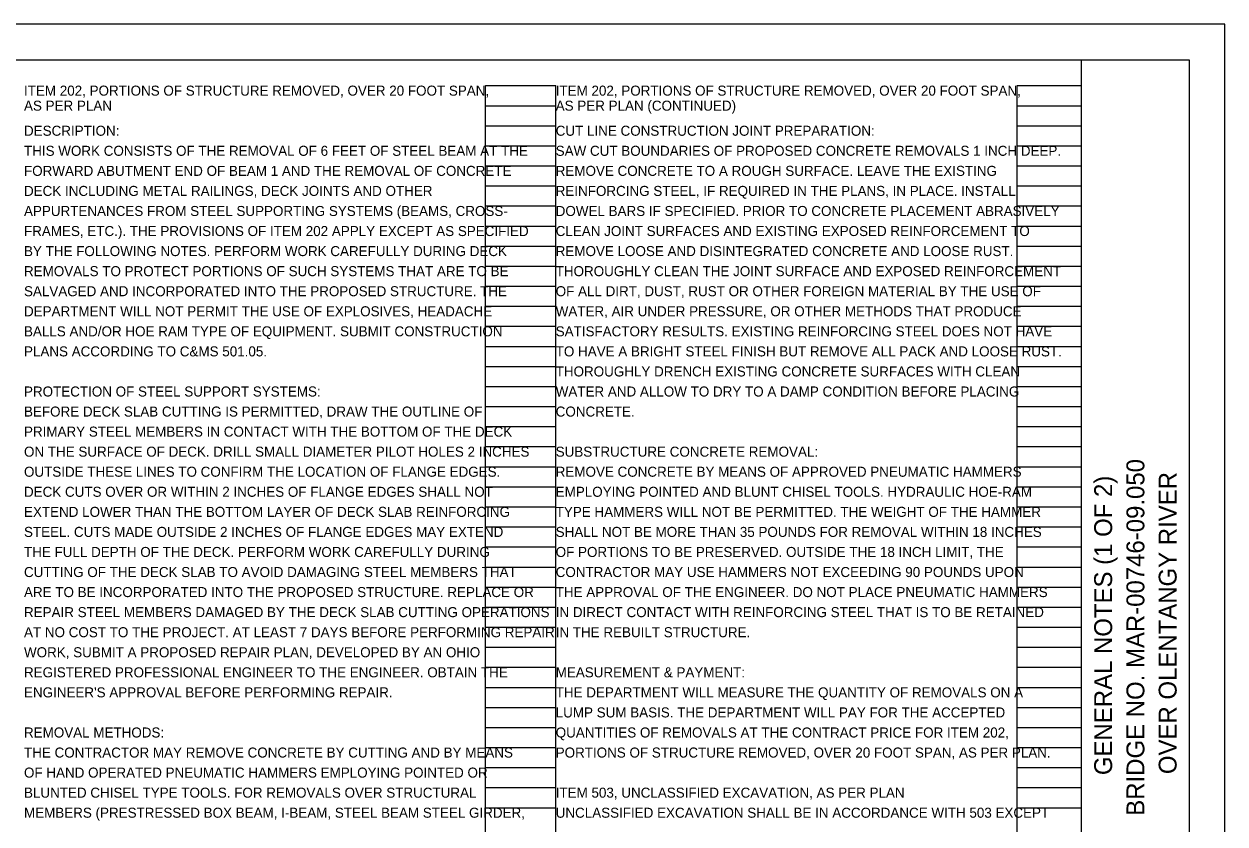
# Model space of a CAD drawing. Extents: x 0 to 34, y 0 to 22.
# Drawn here: x 17.24 to 34, y 10.83 to 22 of the extents above; entities that cross this region are included whole.
import ezdxf

# ---------------------------------------------------------------- set-up
doc = ezdxf.new("R2010")
doc.units = 0
for name, color, linetype in [('SH_Border', 7, 'Continuous'), ('SH_Cut_Line', 7, 'Continuous'), ('SH_Data', 7, 'Continuous'), ('SH_Text', 7, 'Continuous')]:
    doc.layers.add(name, color=color, linetype=linetype)

msp = doc.modelspace()

# ---------------------------------------------------------------- linework, layer by layer
at = {"layer": 'SH_Border'}
msp.add_line((32, 0.5), (32, 21.5), dxfattribs=at)
msp.add_lwpolyline([(1.5, 21.5), (33.5, 21.5), (33.5, 0.5), (1.5, 0.5)], close=True, dxfattribs=at)
at = {"layer": 'SH_Cut_Line'}
msp.add_lwpolyline([(0, 0), (34, 0), (34, 22), (0, 22)], close=True, dxfattribs=at)
at = {"layer": 'SH_Data'}
for p, q in [((23.68, 0.98), (23.68, 21.14)), ((23.68, 21.14), (24.66, 21.14)), ((24.66, 0.98), (24.66, 21.14)), ((31.1, 0.98), (31.1, 21.14)), ((31.1, 21.14), (32, 21.14)), ((32, 0.98), (32, 21.14)), ((23.68, 20.86), (24.66, 20.86)), ((31.1, 20.86), (32, 20.86)), ((23.68, 20.58), (24.66, 20.58)), ((31.1, 20.58), (32, 20.58)), ((23.68, 20.3), (24.66, 20.3)), ((31.1, 20.3), (32, 20.3)), ((23.68, 20.02), (24.66, 20.02)), ((31.1, 20.02), (32, 20.02)), ((23.68, 19.74), (24.66, 19.74)), ((31.1, 19.74), (32, 19.74)), ((23.68, 19.46), (24.66, 19.46)), ((31.1, 19.46), (32, 19.46)), ((23.68, 19.18), (24.66, 19.18)), ((31.1, 19.18), (32, 19.18)), ((23.68, 18.9), (24.66, 18.9)), ((31.1, 18.9), (32, 18.9)), ((23.68, 18.62), (24.66, 18.62)), ((31.1, 18.62), (32, 18.62)), ((23.68, 18.34), (24.66, 18.34)), ((31.1, 18.34), (32, 18.34)), ((23.68, 18.06), (24.66, 18.06)), ((31.1, 18.06), (32, 18.06)), ((23.68, 17.78), (24.66, 17.78)), ((31.1, 17.78), (32, 17.78)), ((23.68, 17.5), (24.66, 17.5)), ((31.1, 17.5), (32, 17.5)), ((23.68, 17.22), (24.66, 17.22)), ((31.1, 17.22), (32, 17.22)), ((23.68, 16.94), (24.66, 16.94)), ((31.1, 16.94), (32, 16.94)), ((23.68, 16.66), (24.66, 16.66)), ((31.1, 16.66), (32, 16.66)), ((23.68, 16.38), (24.66, 16.38)), ((31.1, 16.38), (32, 16.38)), ((23.68, 16.1), (24.66, 16.1)), ((31.1, 16.1), (32, 16.1)), ((23.68, 15.82), (24.66, 15.82)), ((31.1, 15.82), (32, 15.82)), ((23.68, 15.54), (24.66, 15.54)), ((31.1, 15.54), (32, 15.54)), ((23.68, 15.26), (24.66, 15.26)), ((31.1, 15.26), (32, 15.26)), ((23.68, 14.98), (24.66, 14.98)), ((31.1, 14.98), (32, 14.98)), ((23.68, 14.7), (24.66, 14.7)), ((31.1, 14.7), (32, 14.7)), ((23.68, 14.42), (24.66, 14.42)), ((31.1, 14.42), (32, 14.42)), ((23.68, 14.14), (24.66, 14.14)), ((31.1, 14.14), (32, 14.14)), ((23.68, 13.86), (24.66, 13.86)), ((31.1, 13.86), (32, 13.86)), ((23.68, 13.58), (24.66, 13.58)), ((31.1, 13.58), (32, 13.58)), ((23.68, 13.3), (24.66, 13.3)), ((31.1, 13.3), (32, 13.3)), ((23.68, 13.02), (24.66, 13.02)), ((31.1, 13.02), (32, 13.02)), ((23.68, 12.74), (24.66, 12.74)), ((31.1, 12.74), (32, 12.74)), ((23.68, 12.46), (24.66, 12.46)), ((31.1, 12.46), (32, 12.46)), ((23.68, 12.18), (24.66, 12.18)), ((31.1, 12.18), (32, 12.18)), ((23.68, 11.9), (24.66, 11.9)), ((31.1, 11.9), (32, 11.9)), ((23.68, 11.62), (24.66, 11.62)), ((31.1, 11.62), (32, 11.62)), ((23.68, 11.34), (24.66, 11.34)), ((31.1, 11.34), (32, 11.34)), ((23.68, 11.06), (24.66, 11.06)), ((31.1, 11.06), (32, 11.06))]:
    msp.add_line(p, q, dxfattribs=at)

# ---------------------------------------------------------------- texts
for s, p in [('BRIDGE NO. MAR-00746-09.050', (32.875, 10.948)), ('GENERAL NOTES (1 OF 2)', (32.425, 11.515)), ('OVER OLENTANGY RIVER', (33.325, 11.529))]:
    msp.add_text(s, height=0.25, rotation=90, dxfattribs=at).set_placement(p)
at = {"layer": 'SH_Text'}
for s, p in [('ITEM 202, PORTIONS OF STRUCTURE REMOVED, OVER 20 FOOT SPAN, ', (17.24, 21)), ('ITEM 202, PORTIONS OF STRUCTURE REMOVED, OVER 20 FOOT SPAN,', (24.66, 21)), ('AS PER PLAN', (17.24, 20.79)), ('AS PER PLAN (CONTINUED)', (24.66, 20.79)), ('DESCRIPTION:', (17.24, 20.44)), ('CUT LINE CONSTRUCTION JOINT PREPARATION:', (24.66, 20.44)), ('THIS WORK CONSISTS OF THE REMOVAL OF 6 FEET OF STEEL BEAM AT THE', (17.24, 20.16)), ('SAW CUT BOUNDARIES OF PROPOSED CONCRETE REMOVALS 1 INCH DEEP. ', (24.66, 20.16)), ('FORWARD ABUTMENT END OF BEAM 1 AND THE REMOVAL OF CONCRETE ', (17.24, 19.88)), ('REMOVE CONCRETE TO A ROUGH SURFACE. LEAVE THE EXISTING ', (24.66, 19.88)), ('DECK INCLUDING METAL RAILINGS, DECK JOINTS AND OTHER ', (17.24, 19.6)), ('REINFORCING STEEL, IF REQUIRED IN THE PLANS, IN PLACE. INSTALL ', (24.66, 19.6)), ('APPURTENANCES FROM STEEL SUPPORTING SYSTEMS (BEAMS, CROSS-', (17.24, 19.32)), ('DOWEL BARS IF SPECIFIED. PRIOR TO CONCRETE PLACEMENT ABRASIVELY', (24.66, 19.32)), ('FRAMES, ETC.). THE PROVISIONS OF ITEM 202 APPLY EXCEPT AS SPECIFIED ', (17.24, 19.04)), ('CLEAN JOINT SURFACES AND EXISTING EXPOSED REINFORCEMENT TO ', (24.66, 19.04)), ('BY THE FOLLOWING NOTES. PERFORM WORK CAREFULLY DURING DECK ', (17.24, 18.76)), ('REMOVE LOOSE AND DISINTEGRATED CONCRETE AND LOOSE RUST. ', (24.66, 18.76)), ('REMOVALS TO PROTECT PORTIONS OF SUCH SYSTEMS THAT ARE TO BE ', (17.24, 18.48)), ('THOROUGHLY CLEAN THE JOINT SURFACE AND EXPOSED REINFORCEMENT ', (24.66, 18.48)), ('SALVAGED AND INCORPORATED INTO THE PROPOSED STRUCTURE. THE ', (17.24, 18.2)), ('OF ALL DIRT, DUST, RUST OR OTHER FOREIGN MATERIAL BY THE USE OF ', (24.66, 18.2)), ('DEPARTMENT WILL NOT PERMIT THE USE OF EXPLOSIVES, HEADACHE ', (17.24, 17.92)), ('WATER, AIR UNDER PRESSURE, OR OTHER METHODS THAT PRODUCE ', (24.66, 17.92)), ('BALLS AND/OR HOE RAM TYPE OF EQUIPMENT. SUBMIT CONSTRUCTION ', (17.24, 17.64)), ('SATISFACTORY RESULTS. EXISTING REINFORCING STEEL DOES NOT HAVE ', (24.66, 17.64)), ('PLANS ACCORDING TO C&MS 501.05.', (17.24, 17.36)), ('TO HAVE A BRIGHT STEEL FINISH BUT REMOVE ALL PACK AND LOOSE RUST.', (24.66, 17.36)), ('THOROUGHLY DRENCH EXISTING CONCRETE SURFACES WITH CLEAN ', (24.66, 17.08)), ('PROTECTION OF STEEL SUPPORT SYSTEMS: ', (17.24, 16.8)), ('WATER AND ALLOW TO DRY TO A DAMP CONDITION BEFORE PLACING ', (24.66, 16.8)), ('BEFORE DECK SLAB CUTTING IS PERMITTED, DRAW THE OUTLINE OF ', (17.24, 16.52)), ('CONCRETE.', (24.66, 16.52)), ('PRIMARY STEEL MEMBERS IN CONTACT WITH THE BOTTOM OF THE DECK ', (17.24, 16.24)), ('ON THE SURFACE OF DECK. DRILL SMALL DIAMETER PILOT HOLES 2 INCHES ', (17.24, 15.96)), ('SUBSTRUCTURE CONCRETE REMOVAL:', (24.66, 15.96)), ('OUTSIDE THESE LINES TO CONFIRM THE LOCATION OF FLANGE EDGES. ', (17.24, 15.68)), ('REMOVE CONCRETE BY MEANS OF APPROVED PNEUMATIC HAMMERS ', (24.66, 15.68)), ('DECK CUTS OVER OR WITHIN 2 INCHES OF FLANGE EDGES SHALL NOT ', (17.24, 15.4)), ('EMPLOYING POINTED AND BLUNT CHISEL TOOLS. HYDRAULIC HOE-RAM ', (24.66, 15.4)), ('EXTEND LOWER THAN THE BOTTOM LAYER OF DECK SLAB REINFORCING ', (17.24, 15.12)), ('TYPE HAMMERS WILL NOT BE PERMITTED. THE WEIGHT OF THE HAMMER ', (24.66, 15.12)), ('STEEL. CUTS MADE OUTSIDE 2 INCHES OF FLANGE EDGES MAY EXTEND ', (17.24, 14.84)), ('SHALL NOT BE MORE THAN 35 POUNDS FOR REMOVAL WITHIN 18 INCHES', (24.66, 14.84)), ('THE FULL DEPTH OF THE DECK. PERFORM WORK CAREFULLY DURING ', (17.24, 14.56)), ('OF PORTIONS TO BE PRESERVED. OUTSIDE THE 18 INCH LIMIT, THE ', (24.66, 14.56)), ('CUTTING OF THE DECK SLAB TO AVOID DAMAGING STEEL MEMBERS THAT ', (17.24, 14.28)), ('CONTRACTOR MAY USE HAMMERS NOT EXCEEDING 90 POUNDS UPON ', (24.66, 14.28)), ('ARE TO BE INCORPORATED INTO THE PROPOSED STRUCTURE. REPLACE OR ', (17.24, 14)), ('THE APPROVAL OF THE ENGINEER. DO NOT PLACE PNEUMATIC HAMMERS ', (24.66, 14)), ('REPAIR STEEL MEMBERS DAMAGED BY THE DECK SLAB CUTTING OPERATIONS ', (17.24, 13.72)), ('IN DIRECT CONTACT WITH REINFORCING STEEL THAT IS TO BE RETAINED ', (24.66, 13.72)), ('AT NO COST TO THE PROJECT. AT LEAST 7 DAYS BEFORE PERFORMING REPAIR ', (17.24, 13.44)), ('IN THE REBUILT STRUCTURE.', (24.66, 13.44)), ('WORK, SUBMIT A PROPOSED REPAIR PLAN, DEVELOPED BY AN OHIO ', (17.24, 13.16)), ('REGISTERED PROFESSIONAL ENGINEER TO THE ENGINEER. OBTAIN THE ', (17.24, 12.88)), ('MEASUREMENT & PAYMENT: ', (24.66, 12.88)), ("ENGINEER'S APPROVAL BEFORE PERFORMING REPAIR.", (17.24, 12.6)), ('THE DEPARTMENT WILL MEASURE THE QUANTITY OF REMOVALS ON A ', (24.66, 12.6)), ('LUMP SUM BASIS. THE DEPARTMENT WILL PAY FOR THE ACCEPTED ', (24.66, 12.32)), ('REMOVAL METHODS: ', (17.24, 12.04)), ('QUANTITIES OF REMOVALS AT THE CONTRACT PRICE FOR ITEM 202, ', (24.66, 12.04)), ('THE CONTRACTOR MAY REMOVE CONCRETE BY CUTTING AND BY MEANS ', (17.24, 11.76)), ('PORTIONS OF STRUCTURE REMOVED, OVER 20 FOOT SPAN, AS PER PLAN. ', (24.66, 11.76)), ('OF HAND OPERATED PNEUMATIC HAMMERS EMPLOYING POINTED OR ', (17.24, 11.48)), ('BLUNTED CHISEL TYPE TOOLS. FOR REMOVALS OVER STRUCTURAL ', (17.24, 11.2)), ('ITEM 503, UNCLASSIFIED EXCAVATION, AS PER PLAN', (24.66, 11.2)), ('MEMBERS (PRESTRESSED BOX BEAM, I-BEAM, STEEL BEAM STEEL GIRDER, ', (17.24, 10.92)), ('UNCLASSIFIED EXCAVATION SHALL BE IN ACCORDANCE WITH 503 EXCEPT', (24.66, 10.92))]:
    msp.add_text(s, height=0.14, dxfattribs=at).set_placement(p)

doc.saveas('drawing.dxf')
